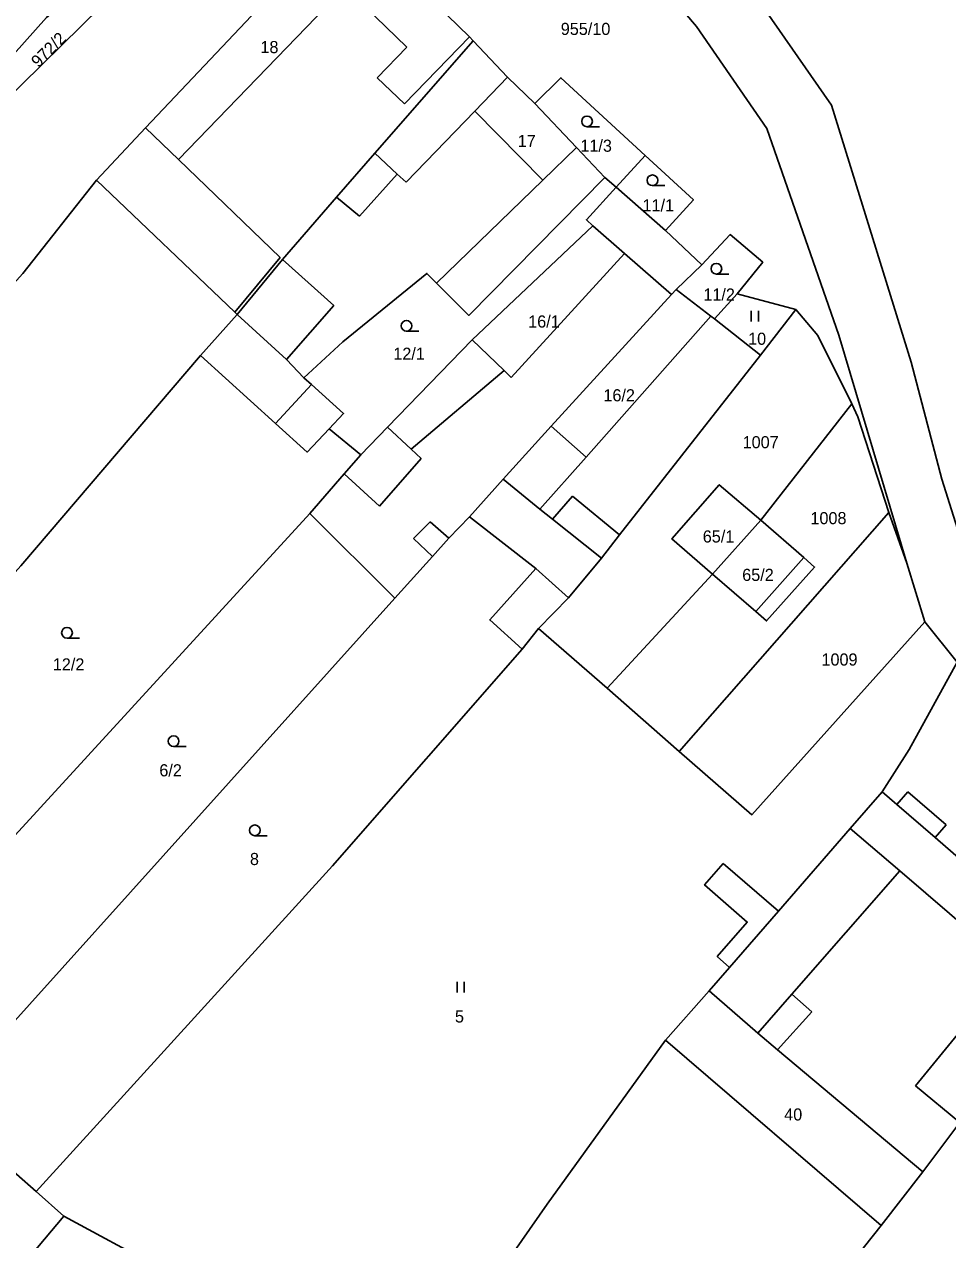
# Model space of a CAD drawing. Extents: x -7483133 to -743169, y -11317770 to -1127091.
# Drawn here: x -747956.4 to -747826.9, y -1131157.3 to -1130986.8 of the extents above; entities that cross this region are included whole.
import ezdxf

# ---------------------------------------------------------------- set-up
doc = ezdxf.new("R2010")
doc.units = 0
for name, color, linetype in [('Hranice parcel', 7, 'Continuous'), ('Parcelní čísla', 7, 'Continuous'), ('Vnitřní kresba', 7, 'Continuous'), ('Značky kultur', 7, 'Continuous')]:
    doc.layers.add(name, color=color, linetype=linetype)

msp = doc.modelspace()

# ---------------------------------------------------------------- linework, layer by layer
at = {"layer": 'Hranice parcel'}
for p, q in [((-747869.31, -1131005.23), (-747873.4, -1131009.7)), ((-747874.96, -1131008.33), (-747873.4, -1131009.7)), ((-747866.49, -1131015.77), (-747873.4, -1131009.7)), ((-747861.39, -1131020.56), (-747866.49, -1131015.77)), ((-747864.99, -1131024.01), (-747861.39, -1131020.56)), ((-747856.43, -1131024.62), (-747859.61, -1131028.15)), ((-747848.2, -1131026.86), (-747856.43, -1131024.62)), ((-747926.54, -1131027.52), (-747931.7, -1131033.31)), ((-747853.12, -1131033.24), (-747859.61, -1131028.15)), ((-747853.12, -1131033.24), (-747848.2, -1131026.86)), ((-747840.33, -1131040.05), (-747853.09, -1131056.39)), ((-747913.66, -1131043.59), (-747909.21, -1131047.2)), ((-747916.37, -1131055.44), (-747981.47, -1131126.53)), ((-747916.37, -1131055.44), (-747904.43, -1131067.33)), ((-747864.53, -1131088.83), (-747835.16, -1131055.31)), ((-747832.63, -1131062.43), (-747835.16, -1131055.31)), ((-747859.86, -1131063.94), (-747853.09, -1131056.39)), ((-747859.86, -1131063.94), (-747874.67, -1131079.94)), ((-747830.09, -1131070.64), (-747832.63, -1131062.43)), ((-747968.37, -1131138.42), (-747904.43, -1131067.33)), ((-747825.56, -1131076.31), (-747830.09, -1131070.64)), ((-747886.56, -1131074.48), (-747884.28, -1131071.56)), ((-747874.67, -1131079.94), (-747884.28, -1131071.56)), ((-747874.67, -1131079.94), (-747864.53, -1131088.83)), ((-747827.12, -1131099.14), (-747832.48, -1131094.48)), ((-747866.49, -1131129.32), (-747836.24, -1131155.33)), ((-747965.44, -1131141.16), (-747954.75, -1131150.54)), ((-747954.75, -1131150.54), (-747950.86, -1131153.99)), ((-747950.86, -1131153.99), (-747934.24, -1131162.98)), ((-747874.56, -1131203.77), (-747836.24, -1131155.33))]:
    msp.add_line(p, q, dxfattribs=at)
for points in [[(-747924.97, -1130956.33), (-747918.19, -1130956.61), (-747897.81, -1130956.39), (-747883.35, -1130957.23), (-747867.68, -1130968.89), (-747853.38, -1130983.52), (-747843.2, -1130998.16), (-747832.03, -1131034.24), (-747827.69, -1131050.62), (-747823.07, -1131065.32)], [(-747832.63, -1131062.43), (-747842.17, -1131030.42), (-747852.24, -1131001.44), (-747862.12, -1130987.14), (-747872.45, -1130974.99), (-747890.11, -1130965.25), (-747905.36, -1130965.53)], [(-747980.93, -1131019.45), (-747968.09, -1131002.39), (-747962.23, -1130995.86), (-747953.3, -1130985.9), (-747936.97, -1130972.39), (-747933.73, -1130969.71), (-747921.38, -1130967.81)], [(-747921.38, -1130967.81), (-747937.31, -1130976.12), (-747967.89, -1131006.15), (-747980.93, -1131019.45)], [(-747911.3, -1130971.64), (-747939.39, -1131001.36), (-747946.28, -1131008.68)], [(-747893.47, -1130989.15), (-747893.98, -1130988.57), (-747901.77, -1130980.96)], [(-747893.47, -1130989.15), (-747907.26, -1131004.91), (-747912.64, -1131011.06), (-747920.21, -1131019.82), (-747926.54, -1131027.52)], [(-747884.79, -1130997.93), (-747888.65, -1130994.25), (-747893.47, -1130989.15)], [(-747869.31, -1131005.23), (-747881.15, -1130994.34), (-747884.79, -1130997.93)], [(-747874.96, -1131008.33), (-747878.95, -1131004.11), (-747884.79, -1130997.93)], [(-747866.49, -1131015.77), (-747862.56, -1131011.46), (-747869.31, -1131005.23)], [(-747946.28, -1131008.68), (-747956.6, -1131021.8), (-747978.68, -1131046.17), (-748020.82, -1131093.67)], [(-747946.28, -1131008.68), (-747926.89, -1131027.23), (-747926.54, -1131027.52)], [(-747913.66, -1131043.59), (-747911.63, -1131041.44), (-747916.14, -1131037.35), (-747917.2, -1131036.42), (-747911.72, -1131031.37), (-747899.94, -1131021.78), (-747898.59, -1131023.13), (-747894.04, -1131027.67), (-747874.96, -1131008.33)], [(-747873.4, -1131009.7), (-747877.57, -1131014.25), (-747876.64, -1131015.12), (-747893.59, -1131031.09), (-747905.46, -1131043.33), (-747909.21, -1131047.2)], [(-747856.43, -1131024.62), (-747852.82, -1131020.21), (-747857.4, -1131016.33), (-747861.39, -1131020.56)], [(-747893.98, -1131055.9), (-747889.22, -1131050.64), (-747882.52, -1131043.19), (-747865.63, -1131024.71), (-747864.99, -1131024.01)], [(-747859.61, -1131028.15), (-747860.09, -1131027.78), (-747864.99, -1131024.01)], [(-747848.2, -1131026.86), (-747845.11, -1131030.47), (-747840.33, -1131040.05)], [(-747931.7, -1131033.31), (-747956.91, -1131062.8), (-747973.31, -1131081.03), (-748002.07, -1131110.77)], [(-747931.7, -1131033.31), (-747921.18, -1131042.84), (-747916.72, -1131046.83), (-747913.66, -1131043.59)], [(-747884.28, -1131071.56), (-747880.08, -1131067.26), (-747875.44, -1131061.71), (-747872.94, -1131058.46), (-747853.12, -1131033.24)], [(-747835.16, -1131055.31), (-747839.47, -1131041.9), (-747840.33, -1131040.05)], [(-747909.21, -1131047.2), (-747911.54, -1131049.89), (-747916.37, -1131055.44)], [(-747853.09, -1131056.39), (-747858.92, -1131051.41), (-747865.56, -1131059.01), (-747859.86, -1131063.94)], [(-747904.43, -1131067.33), (-747899.17, -1131061.48), (-747896.85, -1131058.9), (-747893.98, -1131055.9)], [(-747893.98, -1131055.9), (-747884.64, -1131063.16), (-747891.12, -1131070.38), (-747886.56, -1131074.48)], [(-747853.09, -1131056.39), (-747847.05, -1131061.64), (-747845.55, -1131062.96), (-747852.29, -1131070.52), (-747853.8, -1131069.21), (-747859.86, -1131063.94)], [(-747864.53, -1131088.83), (-747854.37, -1131097.71), (-747830.09, -1131070.64)], [(-747886.56, -1131074.48), (-747913.2, -1131104.85), (-747954.75, -1131150.54)], [(-747825.56, -1131076.31), (-747832.27, -1131088.57), (-747836.06, -1131094.48)], [(-747836.06, -1131094.48), (-747840.55, -1131099.64), (-747850.64, -1131111.24), (-747858.36, -1131104.53)], [(-747832.48, -1131094.48), (-747834.02, -1131096.25), (-747836.06, -1131094.48)], [(-747813.56, -1131114.04), (-747828.66, -1131100.91), (-747827.12, -1131099.14)], [(-747858.36, -1131104.53), (-747860.98, -1131107.54), (-747854.99, -1131112.75), (-747859.21, -1131117.61)], [(-747859.21, -1131117.61), (-747857.48, -1131119.12), (-747860.33, -1131122.39), (-747866.49, -1131129.32)], [(-747866.49, -1131129.32), (-747883.09, -1131152.34), (-747900.11, -1131176.75)], [(-747836.24, -1131155.33), (-747830.35, -1131147.8), (-747825.19, -1131140.88)], [(-748100.59, -1131344.15), (-748079.24, -1131322.55), (-748060.51, -1131299.88), (-748028.05, -1131255.6), (-747998.39, -1131214.99), (-747978.25, -1131186.55), (-747950.86, -1131153.99)]]:
    msp.add_lwpolyline(points, dxfattribs=at)
at = {"layer": 'Vnitřní kresba'}
for p, q in [((-747911.42, -1130981.63), (-747934.8, -1131005.8)), ((-747902.74, -1130990.02), (-747911.42, -1130981.63)), ((-747903.1, -1130998), (-747893.98, -1130988.57)), ((-747906.9, -1130994.33), (-747902.74, -1130990.02)), ((-747903.1, -1130998), (-747906.9, -1130994.33)), ((-747893.21, -1130999.04), (-747888.65, -1130994.25)), ((-747893.21, -1130999.04), (-747902.85, -1131008.98)), ((-747883.69, -1131008.71), (-747893.21, -1130999.04)), ((-747934.8, -1131005.8), (-747939.39, -1131001.36)), ((-747883.69, -1131008.71), (-747878.95, -1131004.11)), ((-747934.8, -1131005.8), (-747920.53, -1131019.55)), ((-747904.09, -1131007.84), (-747907.26, -1131004.91)), ((-747904.09, -1131007.84), (-747909.39, -1131013.75)), ((-747902.85, -1131008.98), (-747904.09, -1131007.84)), ((-747898.59, -1131023.13), (-747883.69, -1131008.71)), ((-747909.39, -1131013.75), (-747912.64, -1131011.06)), ((-747876.64, -1131015.12), (-747872.21, -1131018.98)), ((-747920.53, -1131019.55), (-747926.89, -1131027.23)), ((-747872.21, -1131018.98), (-747888.12, -1131036.37)), ((-747872.21, -1131018.98), (-747865.63, -1131024.71)), ((-747920.21, -1131019.82), (-747913.01, -1131026.29)), ((-747913.01, -1131026.29), (-747919.63, -1131033.85)), ((-747919.63, -1131033.85), (-747926.54, -1131027.52)), ((-747860.09, -1131027.78), (-747877.61, -1131047.54)), ((-747889.12, -1131035.41), (-747893.59, -1131031.09)), ((-747919.63, -1131033.85), (-747917.2, -1131036.42)), ((-747889.12, -1131035.41), (-747902.13, -1131046.44)), ((-747888.12, -1131036.37), (-747889.12, -1131035.41)), ((-747916.14, -1131037.35), (-747921.18, -1131042.84)), ((-747905.46, -1131043.33), (-747902.13, -1131046.44)), ((-747882.52, -1131043.19), (-747877.61, -1131047.54)), ((-747902.13, -1131046.44), (-747900.72, -1131047.72)), ((-747900.72, -1131047.72), (-747906.6, -1131054.43)), ((-747877.61, -1131047.54), (-747884.09, -1131054.83)), ((-747911.54, -1131049.89), (-747906.6, -1131054.43)), ((-747884.09, -1131054.83), (-747889.22, -1131050.64)), ((-747879.51, -1131053.02), (-747882.32, -1131056.24)), ((-747879.51, -1131053.02), (-747872.94, -1131058.46)), ((-747882.32, -1131056.24), (-747884.09, -1131054.83)), ((-747901.84, -1131058.94), (-747899.46, -1131056.62)), ((-747899.46, -1131056.62), (-747896.85, -1131058.9)), ((-747875.44, -1131061.71), (-747882.32, -1131056.24)), ((-747901.84, -1131058.94), (-747899.17, -1131061.48)), ((-747853.8, -1131069.21), (-747847.05, -1131061.64)), ((-747884.64, -1131063.16), (-747880.08, -1131067.26)), ((-747834.02, -1131096.25), (-747828.66, -1131100.91)), ((-747840.55, -1131099.64), (-747833.62, -1131105.57)), ((-747833.62, -1131105.57), (-747848.74, -1131122.86)), ((-747833.62, -1131105.57), (-747817.82, -1131119.12)), ((-747857.48, -1131119.12), (-747850.64, -1131111.24)), ((-747817.82, -1131119.12), (-747831.4, -1131135.72)), ((-747860.33, -1131122.39), (-747853.53, -1131128.35)), ((-747848.74, -1131122.86), (-747853.53, -1131128.35)), ((-747848.74, -1131122.86), (-747845.92, -1131125.34)), ((-747845.92, -1131125.34), (-747850.76, -1131130.67)), ((-747853.53, -1131128.35), (-747850.76, -1131130.67)), ((-747850.76, -1131130.67), (-747830.35, -1131147.8)), ((-747831.4, -1131135.72), (-747825.19, -1131140.88))]:
    msp.add_line(p, q, dxfattribs=at)
at = {"layer": 'Značky kultur'}
for p, q in [((-747877.47, -1131001.2), (-747875.72, -1131001.2)), ((-747868.3, -1131009.46), (-747866.55, -1131009.46)), ((-747859.33, -1131021.87), (-747857.58, -1131021.87)), ((-747854.43, -1131028.52), (-747854.43, -1131027.02)), ((-747853.43, -1131028.52), (-747853.43, -1131027.02)), ((-747902.8, -1131029.88), (-747901.05, -1131029.88)), ((-747950.42, -1131072.93), (-747948.67, -1131072.93)), ((-747935.47, -1131088.14), (-747933.72, -1131088.14)), ((-747924.08, -1131100.64), (-747922.33, -1131100.64)), ((-747895.69, -1131122.62), (-747895.69, -1131121.12)), ((-747894.69, -1131122.62), (-747894.69, -1131121.12))]:
    msp.add_line(p, q, dxfattribs=at)
for centre in [(-747877.47, -1131000.45), (-747868.3, -1131008.71), (-747859.33, -1131021.12), (-747902.8, -1131029.13), (-747950.42, -1131072.18), (-747935.47, -1131087.39), (-747924.08, -1131099.89)]:
    msp.add_circle(centre, 0.75, dxfattribs=at)

# ---------------------------------------------------------------- texts
at = {"layer": 'Parcelní čísla'}
for s, p in [('955/10', (-747881.16, -1130988.33)), ('18', (-747923.29, -1130990.88)), ('17', (-747887.2, -1131004.05)), ('11/3', (-747878.41, -1131004.71)), ('11/1', (-747869.69, -1131013.07)), ('11/2', (-747861.16, -1131025.59)), ('16/1', (-747885.73, -1131029.37)), ('10', (-747854.88, -1131031.79)), ('12/1', (-747904.65, -1131033.89)), ('16/2', (-747875.18, -1131039.72)), ('1007', (-747855.65, -1131046.3)), ('1008', (-747846.14, -1131056.95)), ('65/1', (-747861.24, -1131059.52)), ('65/2', (-747855.71, -1131064.91)), ('12/2', (-747952.41, -1131077.47)), ('1009', (-747844.59, -1131076.78)), ('6/2', (-747937.47, -1131092.32)), ('8', (-747924.76, -1131104.76)), ('5', (-747896, -1131126.85)), ('40', (-747849.82, -1131140.59))]:
    msp.add_text(s, height=1.7, dxfattribs=at).set_placement(p)
msp.add_text('972/2', height=1.7, rotation=45, dxfattribs=at).set_placement((-747954.43, -1130993))

doc.saveas('drawing.dxf')
